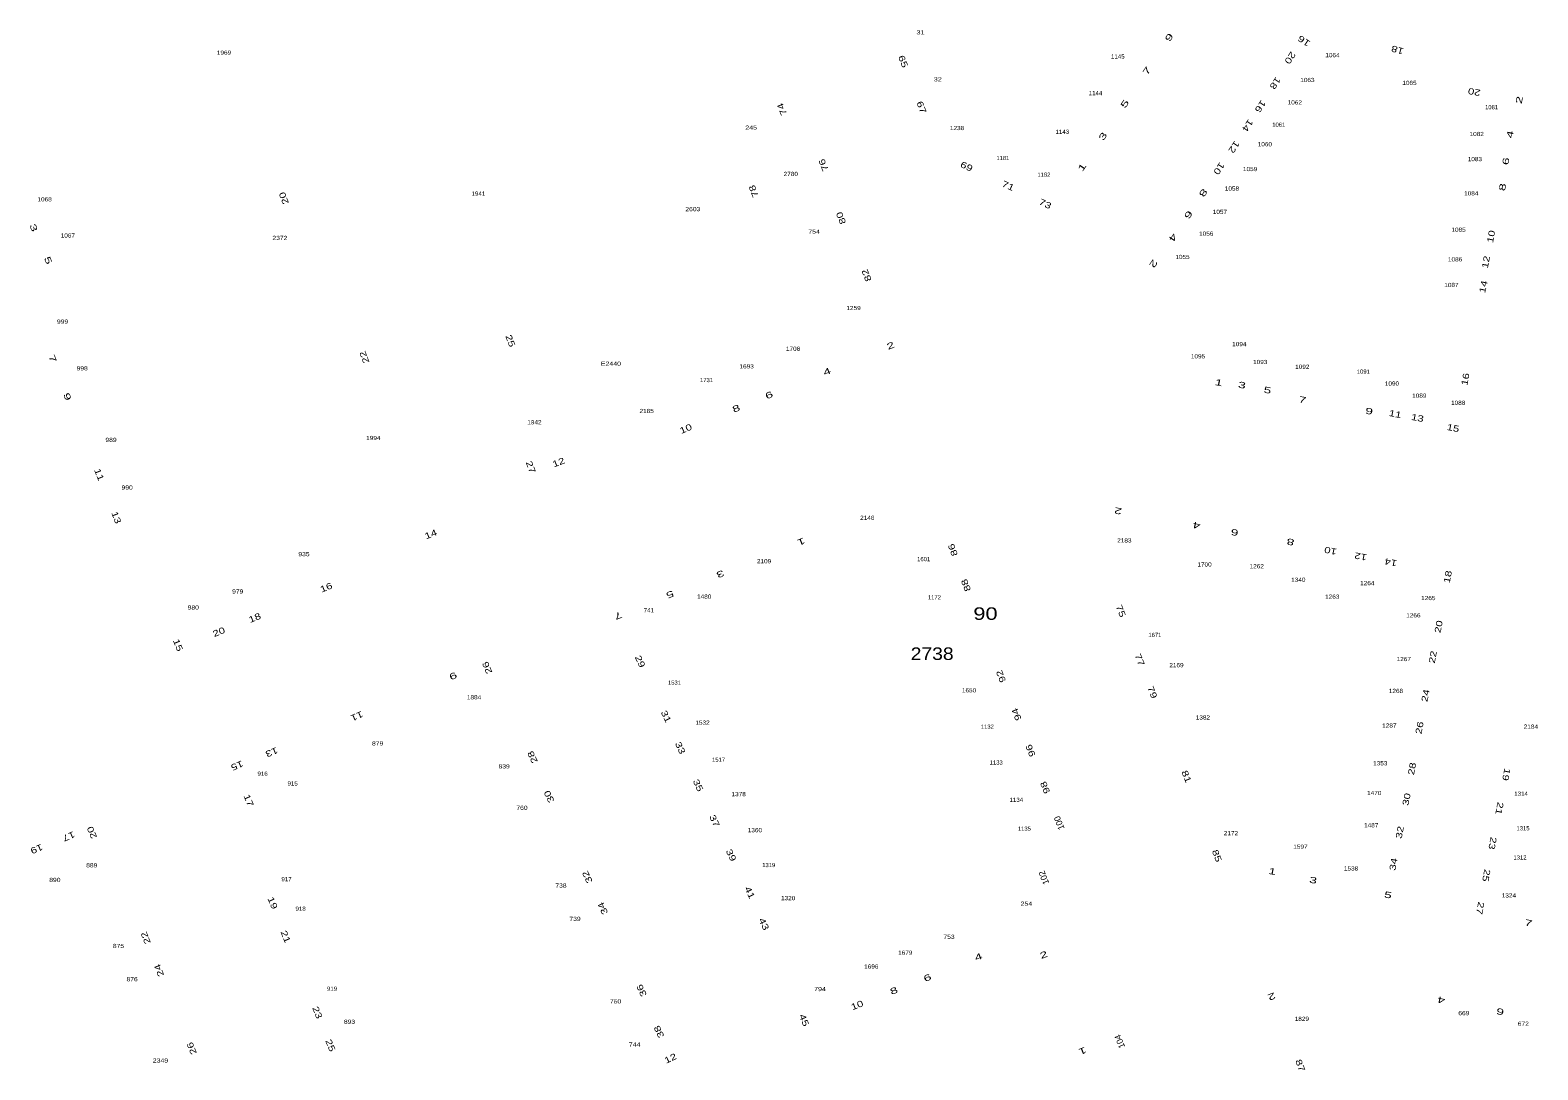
# Model space of a CAD drawing. Extents: x -828673 to -815583, y -1077737 to -1063807.
# Drawn here: x -821834.7 to -821473.8, y -1071604.4 to -1071355.6 of the extents above; entities that cross this region are included whole.
import ezdxf
from ezdxf.enums import TextEntityAlignment as Align

# ---------------------------------------------------------------- set-up
doc = ezdxf.new("R2010")
doc.units = 0
doc.header["$LTSCALE"] = 0.4
doc.layers.add('1', color=7, linetype='Continuous')
doc.layers.add('2', color=7, linetype='Continuous')

msp = doc.modelspace()

# ---------------------------------------------------------------- texts
at = {"layer": '1'}
for s, height, width, p in [('31', 1, 1.3, (-821621.598, -1071356.638)), ('1969', 1, 1.15, (-821788.3, -1071361.508)), ('1145', 1, 1.1, (-821574.374, -1071362.426)), ('1064', 1, 1.15, (-821522.997, -1071362.098)), ('32', 1, 1.3, (-821617.463, -1071367.889)), ('1144', 1, 1.1, (-821579.713, -1071371.186)), ('1063', 1, 1.15, (-821528.998, -1071368.038)), ('1065', 1, 1.15, (-821504.567, -1071368.736)), ('1062', 1, 1.15, (-821532.014, -1071373.407)), ('1081', 1, 1.05, (-821484.914, -1071374.549)), ('245', 1, 1.25, (-821662.136, -1071379.447)), ('1238', 1, 1.15, (-821612.847, -1071379.547)), ('1143', 1, 1.1, (-821587.656, -1071380.437)), ('1061', 1, 1.05, (-821535.851, -1071378.752)), ('1082', 1, 1.15, (-821488.47, -1071380.966)), ('1060', 1, 1.15, (-821539.184, -1071383.421)), ('1083', 1, 1.15, (-821488.92, -1071386.975)), ('2780', 1, 1.15, (-821652.642, -1071390.526)), ('1182', 1, 1.05, (-821592.057, -1071390.696)), ('1059', 1, 1.15, (-821542.709, -1071389.362)), ('1941', 1, 1.1, (-821727.402, -1071395.23)), ('1058', 1, 1.15, (-821547.052, -1071394.011)), ('1084', 1, 1.15, (-821489.778, -1071395.171)), ('1068', 1, 1.15, (-821831.238, -1071396.601)), ('2603', 1, 1.2, (-821676.094, -1071398.954)), ('1057', 1, 1.15, (-821549.942, -1071399.602)), ('1067', 1, 1.15, (-821825.68, -1071405.256)), ('2372', 1, 1.2, (-821774.924, -1071405.843)), ('754', 1, 1.25, (-821647.065, -1071404.341)), ('1056', 1, 1.15, (-821553.212, -1071404.811)), ('1085', 1, 1.15, (-821492.82, -1071403.88)), ('1055', 1, 1.15, (-821558.892, -1071410.391)), ('1086', 1, 1.15, (-821493.646, -1071410.964)), ('1087', 1, 1.15, (-821494.535, -1071417.095)), ('1259', 1, 1.15, (-821637.617, -1071422.609)), ('999', 1, 1.2, (-821826.937, -1071425.871)), ('1708', 1, 1.15, (-821652.095, -1071432.365)), ('1094', 1, 1.15, (-821545.293, -1071431.249)), ('E2440', 1, 1.25, (-821695.687, -1071435.934)), ('1095', 1, 1.15, (-821555.174, -1071434.17)), ('1093', 1, 1.15, (-821540.287, -1071435.527)), ('998', 1, 1.2, (-821822.249, -1071437.041)), ('1693', 1, 1.15, (-821663.208, -1071436.577)), ('1092', 1, 1.15, (-821530.223, -1071436.674)), ('1091', 1, 1.05, (-821515.61, -1071437.832)), ('1731', 1, 1.05, (-821672.802, -1071439.858)), ('1090', 1, 1.15, (-821508.752, -1071440.69)), ('1089', 1, 1.15, (-821502.211, -1071443.581)), ('1088', 1, 1.15, (-821492.909, -1071445.296)), ('1942', 1, 1.15, (-821714.001, -1071449.947)), ('2185', 1, 1.15, (-821687.145, -1071447.254)), ('989', 1, 1.2, (-821815.346, -1071454.17)), ('1994', 1, 1.15, (-821752.564, -1071453.718)), ('990', 1, 1.2, (-821811.48, -1071465.581)), ('2146', 1, 1.15, (-821634.337, -1071472.817)), ('2183', 1, 1.15, (-821572.807, -1071478.229)), ('935', 1, 1.2, (-821769.168, -1071481.521)), ('1601', 1, 1.05, (-821620.839, -1071482.708)), ('2109', 1, 1.15, (-821659.034, -1071483.204)), ('1700', 1, 1.15, (-821553.616, -1071483.989)), ('1262', 1, 1.15, (-821541.116, -1071484.413)), ('1340', 1, 1.15, (-821531.174, -1071487.639)), ('1264', 1, 1.15, (-821514.664, -1071488.45)), ('979', 1, 1.2, (-821785.02, -1071490.467)), ('1480', 1, 1.15, (-821673.374, -1071491.669)), ('1172', 1, 1.05, (-821618.276, -1071491.857)), ('1263', 1, 1.15, (-821523.051, -1071491.683)), ('1265', 1, 1.15, (-821500.052, -1071492.027)), ('980', 1, 1.2, (-821795.652, -1071494.286)), ('741', 1, 1.1, (-821686.628, -1071494.94)), ('1266', 1, 1.15, (-821503.633, -1071496.163)), ('1671', 1, 1.05, (-821565.501, -1071500.845)), ('2738', 3, 1.15, (-821618.809, -1071506.34)), ('2169', 1, 1.15, (-821560.335, -1071508.091)), ('1267', 1, 1.15, (-821505.926, -1071506.622)), ('1531', 1, 1.05, (-821680.487, -1071512.267)), ('1650', 1, 1.15, (-821609.978, -1071514.095)), ('1268', 1, 1.15, (-821507.791, -1071514.243)), ('1884', 1, 1.15, (-821728.459, -1071515.769)), ('1532', 1, 1.15, (-821673.773, -1071521.832)), ('1382', 1, 1.15, (-821554.004, -1071520.599)), ('1287', 1, 1.15, (-821509.381, -1071522.534)), ('1132', 1, 1.05, (-821605.604, -1071522.803)), ('2184', 1, 1.15, (-821475.507, -1071522.788)), ('879', 1, 1.2, (-821751.531, -1071526.805)), ('839', 1, 1.2, (-821721.257, -1071532.303)), ('1517', 1, 1.05, (-821669.929, -1071530.716)), ('1133', 1, 1.05, (-821603.483, -1071531.377)), ('1353', 1, 1.15, (-821511.557, -1071531.554)), ('916', 1, 1.1, (-821779.07, -1071534.047)), ('915', 1, 1.1, (-821771.874, -1071536.388)), ('1378', 1, 1.15, (-821665.121, -1071538.949)), ('1134', 1, 1.1, (-821598.667, -1071540.306)), ('1470', 1, 1.15, (-821512.995, -1071538.669)), ('1314', 1, 1.1, (-821477.853, -1071538.832)), ('760', 1, 1.2, (-821716.989, -1071542.218)), ('1360', 1, 1.15, (-821661.233, -1071547.569)), ('1135', 1, 1.05, (-821596.731, -1071547.208)), ('1487', 1, 1.15, (-821513.726, -1071546.387)), ('1315', 1, 1.05, (-821477.389, -1071547.114)), ('2172', 1, 1.15, (-821547.295, -1071548.296)), ('1597', 1, 1.15, (-821530.662, -1071551.523)), ('1312', 1, 1.05, (-821478.12, -1071554.117)), ('889', 1, 1.2, (-821819.955, -1071555.972)), ('1319', 1, 1.05, (-821657.92, -1071555.923)), ('1538', 1, 1.15, (-821518.545, -1071556.729)), ('890', 1, 1.2, (-821828.782, -1071559.472)), ('917', 1, 1.1, (-821773.337, -1071559.297)), ('738', 1, 1.2, (-821707.655, -1071560.822)), ('1320', 1, 1.15, (-821653.281, -1071563.835)), ('254', 1, 1.25, (-821596.245, -1071565.153)), ('1324', 1, 1.15, (-821480.773, -1071563.186)), ('918', 1, 1.1, (-821769.97, -1071566.365)), ('739', 1, 1.2, (-821704.288, -1071568.792)), ('753', 1, 1.2, (-821614.774, -1071573.09)), ('875', 1, 1.2, (-821813.558, -1071575.277)), ('1679', 1, 1.15, (-821625.244, -1071576.892)), ('1696', 1, 1.15, (-821633.374, -1071580.207)), ('876', 1, 1.2, (-821810.298, -1071583.233)), ('919', 1, 1.1, (-821762.441, -1071585.502)), ('794', 1, 1.25, (-821645.656, -1071585.599)), ('750', 1, 1.2, (-821694.576, -1071588.539)), ('893', 1, 1.2, (-821758.268, -1071593.424)), ('1829', 1, 1.15, (-821530.329, -1071592.717)), ('669', 1, 1.2, (-821491.548, -1071591.359)), ('672', 1, 1.2, (-821477.317, -1071593.888)), ('744', 1, 1.25, (-821690.024, -1071598.881)), ('2349', 1, 1.25, (-821803.505, -1071602.691))]:
    msp.add_text(s, height=height, dxfattribs=dict(at, width=width)).set_placement(p, align=Align.CENTER)
msp.add_text('1181', height=1, dxfattribs=at).set_placement((-821601.89, -1071386.714), align=Align.CENTER)
at = {"layer": '2'}
for s, rotation, width, p in [('9', 56.376, 1.7, (-821561.4695, -1071357.7733)), ('16', 145.72, 1.35, (-821529.3961, -1071357.59)), ('18', 164.393, 1.35, (-821507.2332, -1071359.6363)), ('65', 291.656, 1.35, (-821626.4378, -1071363.3782)), ('20', 236.387, 1.35, (-821533.7374, -1071361.8428)), ('7', 55.91, 1.7, (-821566.8035, -1071365.7849)), ('18', 236.445, 1.35, (-821537.306, -1071367.8994)), ('20', 169.274, 1.35, (-821488.9204, -1071369.671)), ('74', 112.041, 1.35, (-821654.0668, -1071374.289)), ('67', 291.792, 1.35, (-821622.0454, -1071374.3511)), ('5', 56.192, 1.7, (-821572.0968, -1071373.6548)), ('16', 236.31, 1.35, (-821540.863, -1071373.4565)), ('2', 79.228, 1.65, (-821477.5619, -1071372.4752)), ('14', 236.564, 1.35, (-821543.9053, -1071378.0093)), ('3', 56.711, 1.7, (-821577.3325, -1071381.4506)), ('4', 79.404, 1.65, (-821479.7607, -1071380.7069)), ('12', 236.615, 1.35, (-821547.1741, -1071383.1868)), ('76', 112.012, 1.35, (-821644.1181, -1071387.6376)), ('69', 334.871, 1.35, (-821610.885, -1071388.9045)), ('1', 55.94, 1.7, (-821582.3339, -1071388.8315)), ('10', 236.487, 1.35, (-821550.7633, -1071388.3334)), ('6', 79.144, 1.65, (-821480.7755, -1071387.1233)), ('71', 336.026, 1.35, (-821600.9282, -1071393.5379)), ('20', 111.261, 1.35, (-821773.2853, -1071395.5725)), ('78', 111.758, 1.35, (-821660.8306, -1071393.893)), ('8', 236.284, 1.7, (-821554.551, -1071394.1472)), ('8', 79.38, 1.65, (-821481.5713, -1071393.3167)), ('73', 334.507, 1.35, (-821592.0783, -1071397.8476)), ('6', 236.361, 1.7, (-821558.1057, -1071399.3875)), ('3', 291.269, 1.65, (-821834.5554, -1071403.1584)), ('80', 111.577, 1.35, (-821639.9281, -1071400.3083)), ('4', 236.203, 1.7, (-821561.79, -1071404.8503)), ('10', 79.487, 1.35, (-821484.3106, -1071405.1478)), ('5', 291.833, 1.65, (-821831.0714, -1071410.9901)), ('12', 79.148, 1.35, (-821485.5478, -1071411.2472)), ('82', 111.754, 1.35, (-821633.8087, -1071414.0205)), ('2', 236.271, 1.7, (-821566.4542, -1071411.098)), ('14', 77.695, 1.35, (-821486.1682, -1071417.1873)), ('25', 291.27, 1.35, (-821720.4525, -1071430.2254)), ('2', 22.319, 1.65, (-821628.4963, -1071431.8078)), ('7', 292.215, 1.65, (-821830.0063, -1071434.5064)), ('22', 111.292, 1.35, (-821754.02, -1071433.6318)), ('4', 22.214, 1.65, (-821643.7005, -1071438.0233)), ('16', 79.54, 1.35, (-821490.4649, -1071439.2907)), ('6', 22.376, 1.65, (-821657.5555, -1071443.6539)), ('1', 348.939, 1.65, (-821550.3559, -1071440.6917)), ('3', 349.476, 1.65, (-821544.792, -1071441.2911)), ('5', 348.709, 1.65, (-821538.6898, -1071442.4975)), ('9', 291.791, 1.65, (-821826.4812, -1071443.5961)), ('8', 22.039, 1.65, (-821665.4359, -1071446.8412)), ('7', 349.124, 1.65, (-821530.3065, -1071444.8118)), ('9', 349.176, 1.65, (-821514.3613, -1071447.537)), ('11', 348.94, 1.35, (-821508.1189, -1071448.2086)), ('13', 349.519, 1.35, (-821502.7799, -1071449.1396)), ('10', 22.539, 1.35, (-821677.494, -1071451.7006)), ('15', 349.17, 1.35, (-821494.2704, -1071451.5567)), ('27', 291.23, 1.35, (-821715.5636, -1071460.4454)), ('12', 21, 1.35, (-821707.9703, -1071459.7462)), ('11', 291.943, 1.35, (-821818.8685, -1071462.2532)), ('13', 291.268, 1.35, (-821814.7665, -1071472.5115)), ('2', 169.38, 1.65, (-821574.1633, -1071469.9463)), ('4', 169.077, 1.65, (-821555.3999, -1071473.4094)), ('14', 21.559, 1.35, (-821738.5371, -1071476.9473)), ('1', 202.214, 1.65, (-821650.4085, -1071477.3276)), ('6', 170.004, 1.65, (-821546.2808, -1071475.0843)), ('8', 169.599, 1.65, (-821532.9111, -1071477.3759)), ('86', 110.69, 1.35, (-821613.1619, -1071479.749)), ('10', 167.914, 1.35, (-821523.2955, -1071479.4758)), ('12', 169.563, 1.35, (-821516.1071, -1071480.8516)), ('14', 169.001, 1.35, (-821508.8789, -1071482.2459)), ('3', 202.256, 1.65, (-821669.7864, -1071485.0984)), ('18', 79.38, 1.35, (-821494.6707, -1071486.5787)), ('16', 22.515, 1.35, (-821763.5492, -1071489.6804)), ('88', 111.589, 1.35, (-821610.0296, -1071488.192)), ('5', 201.617, 1.65, (-821681.8302, -1071489.9782)), ('18', 22.166, 1.35, (-821780.657, -1071496.937)), ('7', 202.156, 1.65, (-821694.2437, -1071495.0647)), ('75', 291.203, 1.35, (-821574.3371, -1071494.8863)), ('20', 22.274, 1.35, (-821789.2533, -1071500.3205)), ('20', 79.425, 1.35, (-821496.8619, -1071498.5066)), ('15', 291.791, 1.35, (-821799.9955, -1071503.0521)), ('26', 112.515, 1.35, (-821724.6316, -1071507.9182)), ('29', 295.504, 1.35, (-821689.3741, -1071507.0016)), ('77', 291.654, 1.35, (-821569.8309, -1071506.5643)), ('22', 79.563, 1.35, (-821498.2616, -1071505.7779)), ('9', 203.047, 1.65, (-821733.7564, -1071509.4927)), ('92', 111.239, 1.35, (-821601.6406, -1071509.9867)), ('79', 291.801, 1.35, (-821566.7982, -1071514.341)), ('24', 79.106, 1.35, (-821500.0067, -1071514.9932)), ('94', 111.366, 1.35, (-821597.9299, -1071519.0922)), ('11', 202.953, 1.35, (-821756.7655, -1071519.0967)), ('31', 295.364, 1.35, (-821683.1617, -1071520.1767)), ('26', 79.511, 1.35, (-821501.4421, -1071522.7005)), ('13', 202.562, 1.35, (-821777.1587, -1071527.7239)), ('28', 115.501, 1.35, (-821713.7948, -1071529.2924)), ('33', 294.664, 1.35, (-821679.7839, -1071527.6835)), ('96', 111.527, 1.35, (-821594.5739, -1071527.7567)), ('15', 202.568, 1.35, (-821785.4457, -1071530.9321)), ('28', 79.614, 1.35, (-821503.2318, -1071532.4982)), ('19', 259.313, 1.35, (-821482.1029, -1071533.6094)), ('35', 294.931, 1.35, (-821675.4974, -1071536.6559)), ('98', 111.586, 1.35, (-821591.0833, -1071536.5964)), ('81', 291.512, 1.35, (-821558.6264, -1071534.5115)), ('17', 292.756, 1.35, (-821783.0833, -1071540.2349)), ('30', 116.634, 1.35, (-821709.8274, -1071538.7112)), ('30', 79.219, 1.35, (-821504.5465, -1071539.8223)), ('37', 295.458, 1.35, (-821671.5704, -1071545.1536)), ('21', 259.34, 1.35, (-821483.7553, -1071541.7278)), ('20', 112.971, 1.35, (-821819.2312, -1071547.3557)), ('32', 78.69, 1.35, (-821506.1679, -1071547.7366)), ('19', 202.601, 1.35, (-821833.4133, -1071550.8868)), ('17', 203.24, 1.35, (-821825.7376, -1071547.8697)), ('23', 259.157, 1.35, (-821485.399, -1071550.0689)), ('39', 295.944, 1.35, (-821667.5914, -1071553.3759)), ('85', 290.968, 1.35, (-821551.353, -1071553.4581)), ('34', 79.61, 1.35, (-821507.6887, -1071555.3593)), ('32', 115.411, 1.35, (-821700.6757, -1071557.9783)), ('1', 349.241, 1.65, (-821537.5365, -1071557.6759)), ('25', 259.295, 1.35, (-821486.8975, -1071557.7627)), ('41', 295.5, 1.35, (-821663.1212, -1071562.3356)), ('3', 348.648, 1.65, (-821527.7596, -1071559.7714)), ('19', 292.908, 1.35, (-821777.3475, -1071564.7736)), ('34', 115.431, 1.35, (-821696.9782, -1071565.4746)), ('5', 348.781, 1.65, (-821509.8429, -1071563.3083)), ('27', 259.266, 1.35, (-821488.3612, -1071565.6023)), ('43', 294.864, 1.35, (-821659.744, -1071569.8417)), ('7', 348.285, 1.65, (-821476.2358, -1071570.0063)), ('22', 111.801, 1.35, (-821806.3468, -1071572.588)), ('21', 292.051, 1.35, (-821774.2257, -1071572.8404)), ('24', 111.561, 1.35, (-821803.1637, -1071580.3451)), ('4', 21.958, 1.65, (-821607.4674, -1071578.0944)), ('2', 20.768, 1.65, (-821591.8519, -1071577.5912)), ('6', 22.102, 1.65, (-821619.6597, -1071583.089)), ('36', 115.403, 1.35, (-821687.6913, -1071585.1257)), ('8', 21.625, 1.65, (-821627.6999, -1071586.1857)), ('2', 201.624, 1.65, (-821537.8131, -1071586.1843)), ('23', 292.143, 1.35, (-821766.6496, -1071590.9813)), ('10', 21.365, 1.35, (-821636.4972, -1071589.6471)), ('4', 168.643, 1.65, (-821496.8388, -1071587.0125)), ('6', 168.625, 1.65, (-821482.7016, -1071589.7742)), ('38', 115.491, 1.35, (-821683.5206, -1071594.9933)), ('45', 292.074, 1.35, (-821650.1454, -1071592.8006)), ('25', 292.498, 1.35, (-821763.5178, -1071598.857)), ('26', 112.241, 1.35, (-821795.3419, -1071599.0064)), ('12', 25.125, 1.35, (-821681.1409, -1071602.3516)), ('1', 201.85, 1.65, (-821583.0689, -1071599.2068)), ('87', 291.787, 1.35, (-821531.3946, -1071603.6561))]:
    msp.add_text(s, height=1.5, rotation=rotation, dxfattribs=dict(at, width=width)).set_placement(p, align=Align.CENTER)
at = {"layer": '2', "width": 1.3}
msp.add_text('90', height=3, dxfattribs=at).set_placement((-821606.049, -1071496.75), align=Align.CENTER)
at = {"layer": '2'}
for s, rotation, p in [('100', 111.689, (-821587.7187, -1071545.0862)), ('102', 111.877, (-821591.3848, -1071558.1685)), ('104', 111.826, (-821573.2127, -1071597.3583))]:
    msp.add_text(s, height=1.5, rotation=rotation, dxfattribs=at).set_placement(p, align=Align.CENTER)

doc.saveas('drawing.dxf')
